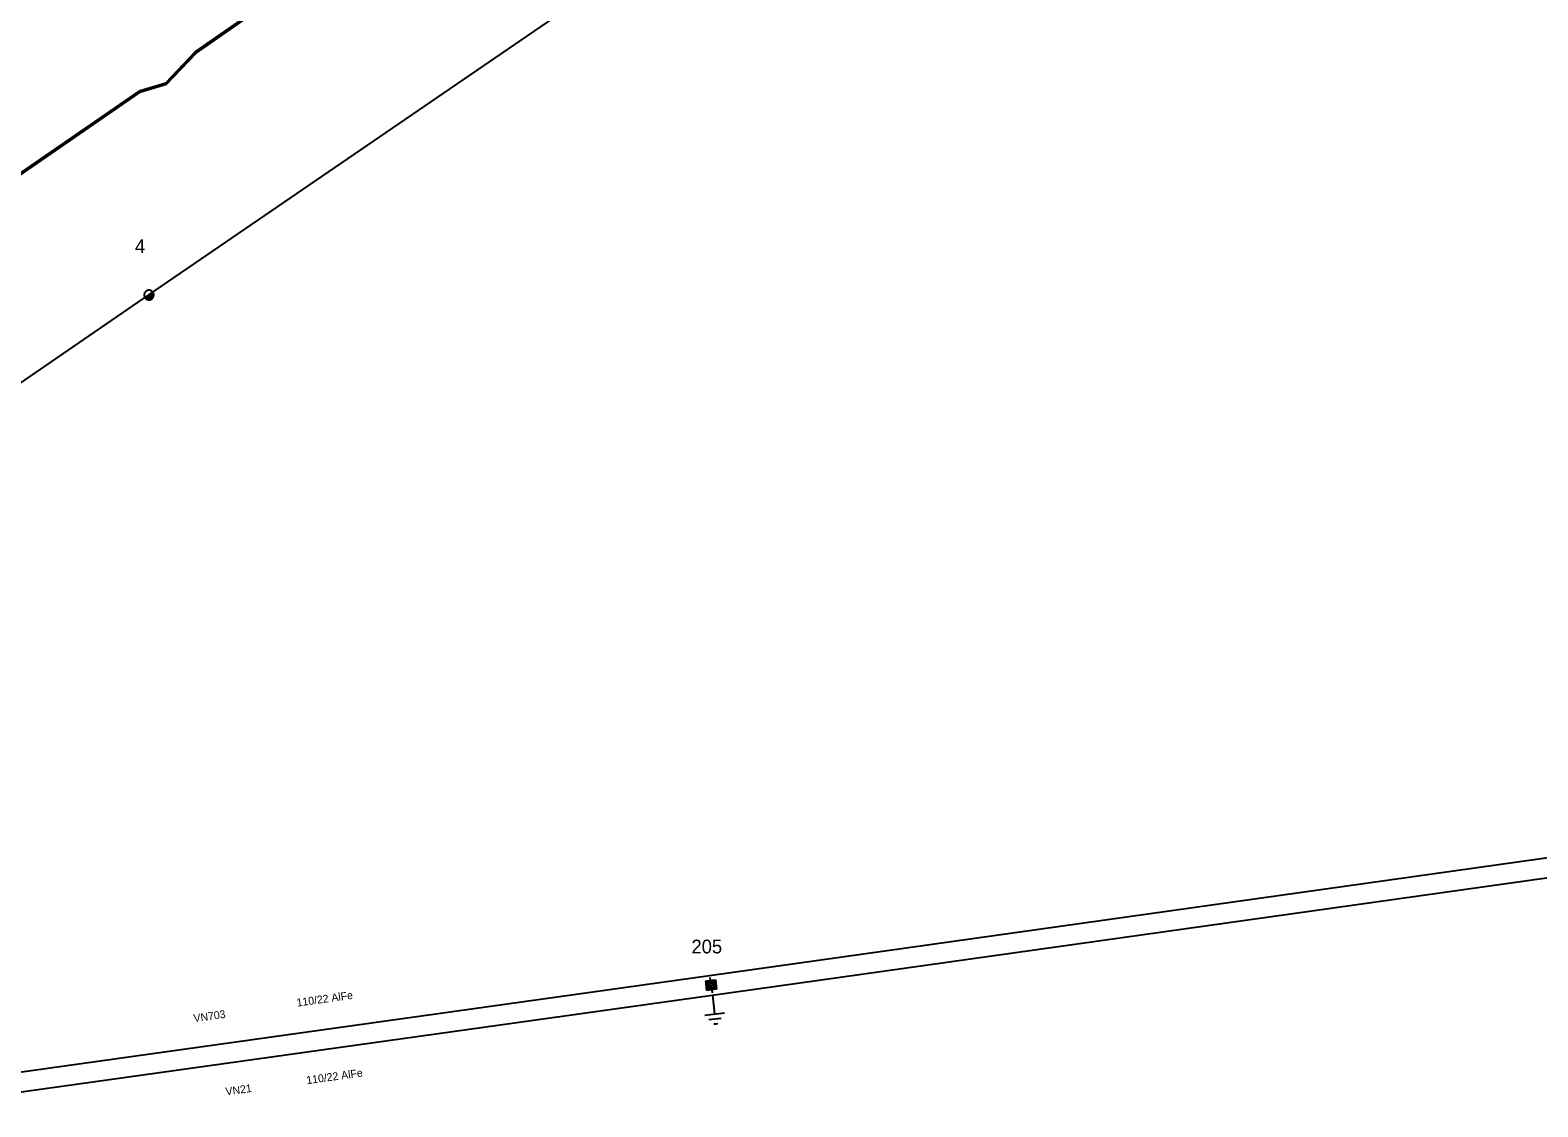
# Model space of a CAD drawing. Extents: x -545588 to -543214, y -1196037 to -1194452.
# Drawn here: x -545008.8 to -544817.1, y -1194901.6 to -1194764.6 of the extents above; entities that cross this region are included whole.
import ezdxf

# ---------------------------------------------------------------- set-up
doc = ezdxf.new("R2010")
doc.units = 0
for name, color, linetype in [('Vrstva 1', 7, 'Continuous'), ('Vrstva 13', 7, 'Continuous'), ('Vrstva 14', 7, 'Continuous'), ('Vrstva 15', 7, 'Continuous'), ('Vrstva 2', 7, 'Continuous'), ('Vrstva 3', 7, 'Continuous'), ('Vrstva 5', 7, 'Continuous')]:
    doc.layers.add(name, color=color, linetype=linetype)

# ---------------------------------------------------------------- blocks, each defined once
blk = doc.blocks.new('VN440')
at = {"layer": 'Vrstva 2'}
for points in [[(1.22, 0), (1.21, 0.13), (1.19, 0.25), (1.16, 0.38), (1.11, 0.5), (1.05, 0.61), (0.98, 0.72), (0.9, 0.82), (0.81, 0.91), (0.71, 0.99), (0.6, 1.06), (0.49, 1.12), (0.37, 1.16), (0.25, 1.2), (0.12, 1.22), (-0.01, 1.22), (-0.14, 1.22), (-0.26, 1.2), (-0.39, 1.16), (-0.51, 1.12), (-0.62, 1.06), (-0.73, 0.99), (-0.83, 0.91), (-0.92, 0.82), (-1, 0.72), (-1.07, 0.61), (-1.13, 0.5), (-1.18, 0.38), (-1.21, 0.25), (-1.23, 0.13), (-1.24, 0), (-1.23, -0.13), (-1.21, -0.26), (-1.18, -0.38), (-1.13, -0.5), (-1.07, -0.62), (-1, -0.73), (-0.92, -0.83), (-0.83, -0.92), (-0.73, -1), (-0.62, -1.07), (-0.51, -1.13), (-0.39, -1.17), (-0.26, -1.2), (-0.14, -1.23), (-0.01, -1.23), (0.12, -1.23), (0.25, -1.2), (0.37, -1.17), (0.49, -1.13), (0.6, -1.07), (0.71, -1), (0.81, -0.92), (0.9, -0.83), (0.98, -0.73), (1.05, -0.62), (1.11, -0.5), (1.16, -0.38), (1.19, -0.26), (1.21, -0.13), (1.22, 0)], [(-1.24, 0), (1.22, 0)], [(-1.18, -0.34), (1.1, -0.34)], [(-1.01, -0.63), (0.97, -0.63)], [(-0.74, -0.92), (0.68, -0.92)]]:
    blk.add_lwpolyline(points, dxfattribs=at)
blk = doc.blocks.new('VN810')
at = {"layer": 'Vrstva 14'}
for points in [[(0, -1.25), (0, -3.75)], [(1.25, -3.75), (-1.25, -3.75)], [(0.77, -4.37), (-0.8, -4.37)], [(0, -5), (-0.25, -5)], [(0.27, -5), (0, -5)]]:
    blk.add_lwpolyline(points, dxfattribs=at)
blk = doc.blocks.new('VN470')
at = {"layer": 'Vrstva 2'}
for points in [[(-1.23, 1.22), (1.23, 1.22)], [(-1.23, -1.23), (-1.23, 1.22)], [(-0.92, 0.9), (0.92, 0.9)], [(-0.92, -0.95), (-0.92, 0.9)], [(-0.61, 0.61), (0.61, 0.61)], [(-0.61, -0.62), (-0.61, 0.61)], [(-0.31, -0.27), (-0.31, 0.34)], [(-0.31, 0.34), (0.31, 0.34)], [(0, 1.22), (0, 1.97)], [(0.31, 0.34), (0.31, -0.27)], [(0.61, 0.61), (0.61, -0.62)], [(0.92, 0.9), (0.92, -0.95)], [(1.23, 1.22), (1.23, -1.23)], [(1.23, -1.23), (-1.23, -1.23)], [(0.92, -0.95), (-0.92, -0.95)], [(0.61, -0.62), (-0.61, -0.62)], [(0.31, -0.27), (-0.31, -0.27)], [(0, -1.23), (0, -1.98)]]:
    blk.add_lwpolyline(points, dxfattribs=at)

msp = doc.modelspace()

# ---------------------------------------------------------------- linework, layer by layer
at = {"layer": 'Vrstva 1'}
for points in [[(-545096.16, -1194848.04), (-545075.95, -1194854.58), (-545032.81, -1194825.14), (-544993.69, -1194798.32), (-544903.01, -1194736.22), (-544804.37, -1194669.21), (-544702.68, -1194600.1), (-544611.95, -1194519.78), (-544514.29, -1194451.62)], [(-544083.88, -1194767.33), (-544137.68, -1194774.97), (-544275.32, -1194794.17), (-544399.3, -1194811.66), (-544539.71, -1194831.51), (-544666.5, -1194849.29), (-544797.03, -1194867.27), (-544922.4, -1194884.94), (-545023.84, -1194899.15), (-545076.32, -1194876.08), (-545112.71, -1194859.53)], [(-545068.12, -1194888.96), (-545023.6, -1194901.6), (-544922.06, -1194887.4), (-544796.64, -1194869.77), (-544666.32, -1194851.78), (-544539.47, -1194833.99), (-544398.96, -1194814.1), (-544275.11, -1194796.62), (-544137.43, -1194777.48), (-544081.81, -1194769.58)]]:
    msp.add_lwpolyline(points, dxfattribs=at)
at = {"layer": 'Vrstva 5'}
for points in [[(-545017.49, -1194788.17), (-544994.72, -1194772.48), (-544991.46, -1194771.51), (-544987.68, -1194767.54), (-544970.83, -1194755.78), (-544959.36, -1194747.87), (-544955.67, -1194746.06), (-544943.12, -1194736.64), (-544921.55, -1194722), (-544915.88, -1194718.94), (-544907.79, -1194712.62), (-544897.27, -1194705.22), (-544885.19, -1194696.78), (-544879.36, -1194692.94), (-544877.31, -1194691.66), (-544872.77, -1194688.49), (-544862.92, -1194681.87), (-544849.13, -1194672.11), (-544823.19, -1194654.37), (-544796.58, -1194635.96)], [(-545233.41, -1194894.88), (-545178.88, -1194890.69), (-545165.68, -1194889.55), (-545162.68, -1194888.62), (-545146.55, -1194877.89), (-545122.2, -1194861.06), (-545095.47, -1194842.73), (-545060.25, -1194817.94), (-545034.96, -1194800.14), (-545017.61, -1194788.01), (-544994.8, -1194772.3), (-544991.56, -1194771.33), (-544987.81, -1194767.38), (-544970.95, -1194755.62), (-544959.46, -1194747.69), (-544955.77, -1194745.88), (-544943.24, -1194736.48), (-544921.65, -1194721.82), (-544915.98, -1194718.78), (-544907.91, -1194712.46), (-544897.39, -1194705.06), (-544885.31, -1194696.62), (-544879.55, -1194692.83), (-544879.87, -1194692.29)]]:
    msp.add_lwpolyline(points, dxfattribs=at)

# ---------------------------------------------------------------- block references
at = {"layer": 'Vrstva 13'}
for name, p, xscale, yscale, rotation in [('VN440', (-544993.69, -1194798.32), 0.5, 0.5, 34.434347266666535), ('VN470', (-544922.19, -1194886.1), 0.49999999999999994, 0.4999999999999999, 6.796644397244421)]:
    msp.add_blockref(name, p, dxfattribs=dict(at, xscale=xscale, yscale=yscale, rotation=rotation))
at = {"layer": 'Vrstva 15', "rotation": 6.791966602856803}
msp.add_blockref('VN810', (-544922.19, -1194886.1), dxfattribs=at)

# ---------------------------------------------------------------- texts
at = {"layer": 'Vrstva 14'}
for s, p in [('4', (-544995.48, -1194792.98)), ('205', (-544924.7, -1194882.08))]:
    msp.add_text(s, height=1.75, dxfattribs=at).set_placement(p)
at = {"layer": 'Vrstva 2'}
for rotation, p in [(7.976, (-544974.84, -1194888.85)), (7.963, (-544973.6, -1194898.72))]:
    msp.add_text('110/22 AlFe', height=1, rotation=rotation, dxfattribs=at).set_placement(p)
at = {"layer": 'Vrstva 3'}
for s, rotation, p in [('VN703', 7.976, (-544987.95, -1194890.84)), ('VN21', 7.963, (-544983.88, -1194900.16))]:
    msp.add_text(s, height=1, rotation=rotation, dxfattribs=at).set_placement(p)

doc.saveas('drawing.dxf')
